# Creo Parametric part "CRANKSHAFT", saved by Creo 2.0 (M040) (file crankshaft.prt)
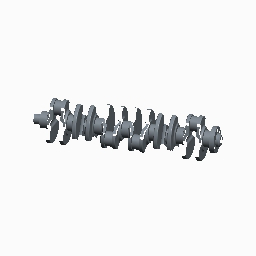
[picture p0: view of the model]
Units: millimeter Kilogram Sec (mmKs); MM, KILOGRAM, SECS

Created from: INLBS_PART_SOLID.PRT

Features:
  1. datum plane "RIGHT"
  2. datum plane "TOP"
  3. datum plane "FRONT"
  4. coordinate system
  5. group "LOCAL_GROUP_1"
  6. group "LOCAL_GROUP"
  7. sketch "Sketch 1"
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
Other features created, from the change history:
  extrusion "Extrude 1"
  extruded cut "Extrude 2"
  hole "Hole 1" (2 times)
  extrusion "Extrude 3"
  extruded cut "Extrude 4"
  round "Round 1"
  round "Round 2"
  round "Round 3"
  round "Round 4"
  round "Round 5"
  round "Round 6"
  round "Round 7"
  extrusion "Extrude 5"
  mirror "Mirror 1"
  group "COPIED_GROUP"
  sketch "Sketch 1 (2)"
  extrusion "Extrude 1 (2)"
  extruded cut "Extrude 2 (2)"
  hole "Hole 1 (2)"
  extrusion "Extrude 3 (2)"
  extruded cut "Extrude 4 (2)"
  round "Round 1 (2)"
  round "Round 2 (2)"
  round "Round 3 (2)"
  round "Round 4 (2)"
  round "Round 5 (2)"
  round "Round 6 (2)"
  round "Round 7 (2)"
  extrusion "Extrude 5 (2)"
  extrusion "Extrude 31"
  pattern "Pattern 1"
  extrusion "Extrude 31 [2]"
  extrusion "Extrude 31 [3]"
  extrusion "Extrude 31 [4]"
  extrusion "Extrude 31 [5]"
  extrusion "Extrude 31 [6]"
  extrusion "Extrude 31 [7]"
  extrusion "Extrude 32"
  extrusion "Extrude 33"
  extrusion "Extrude 34"
  chamfer "Chamfer 1"
  hole "Hole 7"
  pattern "Pattern 2"
  hole "Hole 7 [2]"
  hole "Hole 7 [3]"
  hole "Hole 7 [4]"
  hole "Hole 7 [5]"
  hole "Hole 7 [6]"
  datum axis "SHAFT"

Other named items: COPIED_GROUP_1, LOCAL_GROUP_2, LOCAL_GROUP_3, LOCAL_GROUP_4, COPIED_GROUP_2, LOCAL_GROUP_5, LOCAL_GROUP_6, LOCAL_GROUP_7, COPIED_GROUP_3, LOCAL_GROUP_8, LOCAL_GROUP_9, LOCAL_GROUP_10, COPIED_GROUP_4, LOCAL_GROUP_11, LOCAL_GROUP_12, LOCAL_GROUP_13, COPIED_GROUP_5, LOCAL_GROUP_14, LOCAL_GROUP_15, LOCAL_GROUP_16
